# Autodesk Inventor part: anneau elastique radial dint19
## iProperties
Author: chr
Created: 2002-03
Part Number: anneau elastique radial dint19
Material: Par défaut
Document SubType Name: Modélisation
Designer: chr
Control State: 0
Master: False
Checked Out: False
PropertySet Name: Design Tracking Control
Shininess: 20.0
Angle Display Precision: 2
Document Length Units: 11269
Document Angle Units: 11283
Document Time Units: 11279
Document Mass Units: 11290
Document Length Units Precision: 3
Document Angle Units Precision: 2
Compacted: False
PropertySet Name: _Private Model Information
Density: 0.0
Volumn: 0.0
Area: 0.0
PropertySet Name: Model Information
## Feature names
1. Base1
